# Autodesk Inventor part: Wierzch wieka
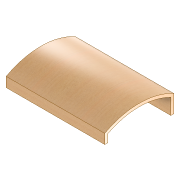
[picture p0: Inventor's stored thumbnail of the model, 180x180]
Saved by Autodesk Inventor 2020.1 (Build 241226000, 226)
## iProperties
Created: 2005-09
Part Number: Wierzch wieka
Document SubType Name: Modeling
Designer: F.Stasiak
Density: 1 g/cm^3
Material: Ogólny
Appearance: Sosna żółta — pełna — barwiona na jasno — niski połysk
Manager: www.cadconsulting.pl
Company: Fabian Stasiak CAD Consulting
Author: F.Stasiak
Subject: Zbiór ćwiczeń. Autodesk Inventor 2020. Kurs podstawowy
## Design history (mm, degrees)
sketch "Szkic2"
  geometry: L1 (-160, 40)-(-160, 0); L2 (160, -40)-(160, 40); L3 (-160, 0)-(160, 0); L4 (175, -40)-(175, 49.025); L5 (-175, 49.025)-(-175, 0); L6 (-160, 0)-(-175, 0); L7 (160, -40)-(175, -40); A1 r 350 centre (0, -271.288) between (160, 40) and (-160, 40); A2 r 365 centre (0, -271.288) between (175, 49.025) and (-175, 49.025); 2 further points
  constraints: 14 end point, 4 point on circle, 3 vertical, 2 centre point, 2 midpoint, 2 parallel, 2 perpendicular, 1 coincident, 1 other
  dimensions: "d7" = 40 distance of L1.start L1.end; "d11" = 40 distance from line of L2.end L3 (= d7); "d12" = 350 radius of A1; "d13" = 80 distance of L2.start L2.end; "d14" = 15 distance of L1.end L5.end; "d15" = 350 distance between parallel lines of L4 L5
extrude "Wyciągnięcie proste2" new body sketch "Szkic2" stored distance "d16" = 500; taper "d17" = 0 deg
node "Bryła1"
node "Korpusy bryłowe"
node "Korpusy powierzchniowe"
